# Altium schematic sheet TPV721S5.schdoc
size 127 x 101 mm
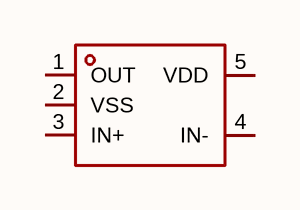
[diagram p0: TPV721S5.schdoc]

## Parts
U?  tpv721s5  [SOT-23-5_L2.9-W1.6-P0.95-LS2.8-BL]  (value not drawn)

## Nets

Not connected (* = marked no-connect by the designer): U? 1(OUT) 2(VSS) 3(IN+) 4(IN-) 5(VDD)

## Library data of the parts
U? = tpv721s5: 放大器数:1;轨到轨:轨到轨输入,轨到轨输出;增益带宽积(GBW):10MHz;输入失调电压(Vos):5mV;压摆率(SR):4.5V/us;输入偏置电流(Ib):1pA;; Manufacturer: TECH PUBLIC(台舟); AddInBom: yes; ModelId: 018c57e721114987ae90467fe9f1d259; ModelTransform: 114.96,110.236,0,0,0,0,0,0,0; Number of Channels: 1; Gain Bandwidth Product: 10MHz; Vos - Input Offset Voltage: 5mV; Input Offset Voltage Drift(Vos TC): 300nV/℃; Ib - Input Bias Current: 1pA; Input Voltage Noise Density: 30nV/√Hz@1kHz; Common Mode Rejection Ratio(CMRR): 75dB; Quiescent Current: 800uA; Output Current: 50mA; Single supply: 2.2V~5.5V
